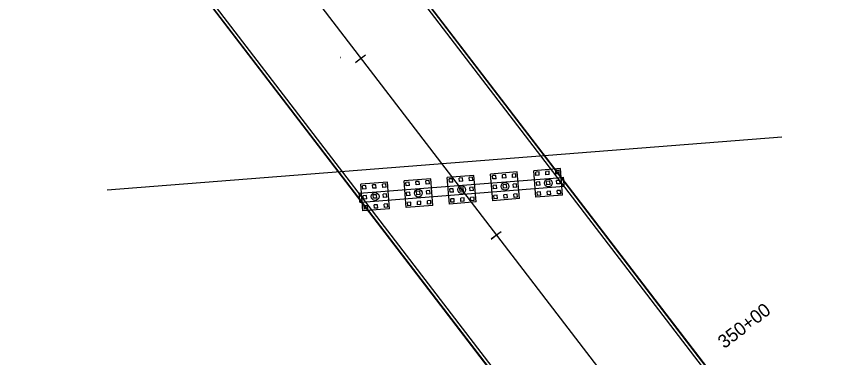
# Model space of a CAD drawing. Extents: x 881426 to 887360, y 1564404 to 1567430.
# Drawn here: x 884000 to 884363.6, y 1565295.5 to 1565449 of the extents above; entities that cross this region are included whole.
import ezdxf

# ---------------------------------------------------------------- set-up
doc = ezdxf.new("R2010")
doc.units = 0
for name, color, linetype in [('B_Concrete', 7, 'Continuous'), ('B_Concrete hidden', 7, 'Continuous'), ('R_Horz Alg', 7, 'Continuous'), ('R_Horz Alg Annot', 7, 'Continuous'), ('S_EXIST_ROW', 7, 'Continuous'), ('S_MSC_PT_SYM', 7, 'Continuous')]:
    doc.layers.add(name, color=color, linetype=linetype)

msp = doc.modelspace()

# ---------------------------------------------------------------- linework, layer by layer
at = {"layer": 'B_Concrete'}
for p, q in [((884362.37, 1565220.93), (884071.12, 1565600.88)), ((884363.42, 1565221.74), (884072.18, 1565601.69)), ((884363.42, 1565221.74), (884072.18, 1565601.69)), ((884363.56, 1565221.85), (884072.31, 1565601.79)), ((884302.84, 1565175.31), (884011.59, 1565555.25)), ((884301.65, 1565174.39), (884010.4, 1565554.34)), ((884301.78, 1565174.49), (884010.54, 1565554.44)), ((884301.78, 1565174.49), (884010.54, 1565554.44)), ((884244.95, 1565376.57), (884245.75, 1565376.63)), ((884245.84, 1565375.41), (884245.75, 1565376.63)), ((884154.34, 1565365.47), (884154.24, 1565366.69)), ((884154.34, 1565365.47), (884155.13, 1565365.53))]:
    msp.add_line(p, q, dxfattribs=at)
at = {"layer": 'B_Concrete hidden'}
for p, q in [((884244.44, 1565380.54), (884232.47, 1565379.61)), ((884245.37, 1565368.58), (884244.44, 1565380.54)), ((884154.03, 1565369.46), (884244.95, 1565376.57)), ((884205.55, 1565377.5), (884193.59, 1565376.57)), ((884194.53, 1565364.6), (884193.59, 1565376.57)), ((884204.87, 1565376.7), (884203.37, 1565376.58)), ((884203.49, 1565375.08), (884203.37, 1565376.58)), ((884204.98, 1565375.2), (884204.87, 1565376.7)), ((884206.49, 1565365.54), (884205.55, 1565377.5)), ((884225, 1565379.02), (884213.03, 1565378.09)), ((884213.97, 1565366.12), (884213.03, 1565378.09)), ((884215.33, 1565377.51), (884213.84, 1565377.4)), ((884213.96, 1565375.9), (884213.84, 1565377.4)), ((884215.45, 1565376.02), (884215.33, 1565377.51)), ((884219.82, 1565377.87), (884218.32, 1565377.75)), ((884218.44, 1565376.25), (884218.32, 1565377.75)), ((884219.94, 1565376.37), (884219.82, 1565377.87)), ((884224.31, 1565378.22), (884222.81, 1565378.1)), ((884222.93, 1565376.6), (884222.81, 1565378.1)), ((884224.42, 1565376.72), (884222.93, 1565376.6)), ((884224.42, 1565376.72), (884224.31, 1565378.22)), ((884225.93, 1565367.06), (884225, 1565379.02)), ((884233.41, 1565367.64), (884232.47, 1565379.61)), ((884234.77, 1565379.03), (884233.28, 1565378.92)), ((884233.4, 1565377.42), (884233.28, 1565378.92)), ((884234.89, 1565377.54), (884233.4, 1565377.42)), ((884234.89, 1565377.54), (884234.77, 1565379.03)), ((884239.26, 1565379.39), (884237.77, 1565379.27)), ((884237.88, 1565377.77), (884237.77, 1565379.27)), ((884239.38, 1565377.89), (884237.88, 1565377.77)), ((884239.38, 1565377.89), (884239.26, 1565379.39)), ((884243.75, 1565379.74), (884242.25, 1565379.62)), ((884242.37, 1565378.12), (884242.25, 1565379.62)), ((884243.86, 1565378.24), (884242.37, 1565378.12)), ((884243.86, 1565378.24), (884243.75, 1565379.74)), ((884166.67, 1565374.46), (884154.71, 1565373.53)), ((884155.65, 1565361.56), (884154.71, 1565373.53)), ((884157.01, 1565372.95), (884155.52, 1565372.84)), ((884155.63, 1565371.34), (884155.52, 1565372.84)), ((884157.13, 1565371.46), (884157.01, 1565372.95)), ((884161.5, 1565373.3), (884160, 1565373.19)), ((884160.12, 1565371.69), (884160, 1565373.19)), ((884161.62, 1565371.81), (884161.5, 1565373.3)), ((884165.98, 1565373.65), (884164.49, 1565373.54)), ((884164.61, 1565372.04), (884164.49, 1565373.54)), ((884166.1, 1565372.16), (884165.98, 1565373.65)), ((884167.61, 1565362.5), (884166.67, 1565374.46)), ((884186.11, 1565375.98), (884174.15, 1565375.05)), ((884175.09, 1565363.08), (884174.15, 1565375.05)), ((884176.45, 1565374.47), (884174.96, 1565374.36)), ((884175.07, 1565372.86), (884174.96, 1565374.36)), ((884176.57, 1565372.98), (884175.07, 1565372.86)), ((884176.57, 1565372.98), (884176.45, 1565374.47)), ((884180.94, 1565374.82), (884179.44, 1565374.71)), ((884179.56, 1565373.21), (884179.44, 1565374.71)), ((884181.06, 1565373.33), (884179.56, 1565373.21)), ((884181.06, 1565373.33), (884180.94, 1565374.82)), ((884185.43, 1565375.18), (884183.93, 1565375.06)), ((884184.05, 1565373.56), (884183.93, 1565375.06)), ((884185.54, 1565373.68), (884184.05, 1565373.56)), ((884185.54, 1565373.68), (884185.43, 1565375.18)), ((884187.05, 1565364.02), (884186.11, 1565375.98)), ((884195.89, 1565375.99), (884194.4, 1565375.88)), ((884194.51, 1565374.38), (884194.4, 1565375.88)), ((884196.01, 1565374.5), (884194.51, 1565374.38)), ((884196.01, 1565374.5), (884195.89, 1565375.99)), ((884200.38, 1565376.34), (884198.88, 1565376.23)), ((884199, 1565374.73), (884198.88, 1565376.23)), ((884200.5, 1565374.85), (884199, 1565374.73)), ((884200.5, 1565374.85), (884200.38, 1565376.34)), ((884204.98, 1565375.2), (884203.49, 1565375.08)), ((884215.45, 1565376.02), (884213.96, 1565375.9)), ((884215.68, 1565373.03), (884214.19, 1565372.91)), ((884214.31, 1565371.42), (884214.19, 1565372.91)), ((884215.8, 1565371.53), (884215.68, 1565373.03)), ((884219.94, 1565376.37), (884218.44, 1565376.25)), ((884220.17, 1565373.38), (884218.68, 1565373.26)), ((884218.79, 1565371.77), (884218.68, 1565373.26)), ((884220.29, 1565371.88), (884220.17, 1565373.38)), ((884224.66, 1565373.73), (884223.16, 1565373.61)), ((884223.28, 1565372.12), (884223.16, 1565373.61)), ((884224.77, 1565372.23), (884224.66, 1565373.73)), ((884235.13, 1565374.55), (884233.63, 1565374.43)), ((884233.75, 1565372.94), (884233.63, 1565374.43)), ((884235.24, 1565373.05), (884233.75, 1565372.94)), ((884235.24, 1565373.05), (884235.13, 1565374.55)), ((884239.61, 1565374.9), (884238.12, 1565374.78)), ((884238.23, 1565373.29), (884238.12, 1565374.78)), ((884239.73, 1565373.4), (884238.23, 1565373.29)), ((884239.73, 1565373.4), (884239.61, 1565374.9)), ((884244.1, 1565375.25), (884242.6, 1565375.13)), ((884242.72, 1565373.64), (884242.6, 1565375.13)), ((884244.21, 1565373.75), (884242.72, 1565373.64)), ((884244.21, 1565373.75), (884244.1, 1565375.25)), ((884246.06, 1565372.65), (884245.84, 1565375.41)), ((884154.24, 1565366.69), (884154.03, 1565369.46)), ((884155.13, 1565365.53), (884246.06, 1565372.65)), ((884157.13, 1565371.46), (884155.63, 1565371.34)), ((884161.62, 1565371.81), (884160.12, 1565371.69)), ((884166.1, 1565372.16), (884164.61, 1565372.04)), ((884176.8, 1565369.99), (884175.31, 1565369.87)), ((884175.42, 1565368.37), (884175.31, 1565369.87)), ((884176.92, 1565368.49), (884176.8, 1565369.99)), ((884181.29, 1565370.34), (884179.79, 1565370.22)), ((884179.91, 1565368.73), (884179.79, 1565370.22)), ((884181.41, 1565368.84), (884181.29, 1565370.34)), ((884185.78, 1565370.69), (884184.28, 1565370.57)), ((884184.4, 1565369.08), (884184.28, 1565370.57)), ((884185.89, 1565369.19), (884184.4, 1565369.08)), ((884185.89, 1565369.19), (884185.78, 1565370.69)), ((884196.24, 1565371.51), (884194.75, 1565371.39)), ((884194.87, 1565369.9), (884194.75, 1565371.39)), ((884196.36, 1565370.01), (884194.87, 1565369.9)), ((884196.36, 1565370.01), (884196.24, 1565371.51)), ((884200.73, 1565371.86), (884199.23, 1565371.74)), ((884199.35, 1565370.25), (884199.23, 1565371.74)), ((884200.85, 1565370.36), (884199.35, 1565370.25)), ((884200.85, 1565370.36), (884200.73, 1565371.86)), ((884205.22, 1565372.21), (884203.72, 1565372.09)), ((884203.84, 1565370.6), (884203.72, 1565372.09)), ((884205.33, 1565370.71), (884203.84, 1565370.6)), ((884205.33, 1565370.71), (884205.22, 1565372.21)), ((884215.8, 1565371.53), (884214.31, 1565371.42)), ((884220.29, 1565371.88), (884218.79, 1565371.77)), ((884224.77, 1565372.23), (884223.28, 1565372.12)), ((884225.01, 1565369.24), (884223.51, 1565369.13)), ((884225.13, 1565367.75), (884225.01, 1565369.24)), ((884235.48, 1565370.06), (884233.98, 1565369.95)), ((884234.1, 1565368.45), (884233.98, 1565369.95)), ((884235.59, 1565368.57), (884235.48, 1565370.06)), ((884239.96, 1565370.41), (884238.47, 1565370.3)), ((884238.58, 1565368.8), (884238.47, 1565370.3)), ((884240.08, 1565368.92), (884239.96, 1565370.41)), ((884244.45, 1565370.76), (884242.95, 1565370.65)), ((884243.07, 1565369.15), (884242.95, 1565370.65)), ((884244.57, 1565369.27), (884243.07, 1565369.15)), ((884244.57, 1565369.27), (884244.45, 1565370.76)), ((884157.36, 1565368.47), (884155.87, 1565368.35)), ((884155.98, 1565366.85), (884155.87, 1565368.35)), ((884157.48, 1565366.97), (884155.98, 1565366.85)), ((884157.48, 1565366.97), (884157.36, 1565368.47)), ((884161.85, 1565368.82), (884160.35, 1565368.7)), ((884160.47, 1565367.2), (884160.35, 1565368.7)), ((884161.97, 1565367.32), (884160.47, 1565367.2)), ((884161.97, 1565367.32), (884161.85, 1565368.82)), ((884166.34, 1565369.17), (884164.84, 1565369.05)), ((884164.96, 1565367.56), (884164.84, 1565369.05)), ((884166.45, 1565367.67), (884164.96, 1565367.56)), ((884166.45, 1565367.67), (884166.34, 1565369.17)), ((884176.92, 1565368.49), (884175.42, 1565368.37)), ((884181.41, 1565368.84), (884179.91, 1565368.73)), ((884181.64, 1565365.85), (884180.15, 1565365.73)), ((884180.26, 1565364.24), (884180.15, 1565365.73)), ((884181.76, 1565364.36), (884181.64, 1565365.85)), ((884186.13, 1565366.2), (884184.63, 1565366.09)), ((884184.75, 1565364.59), (884184.63, 1565366.09)), ((884186.24, 1565364.71), (884186.13, 1565366.2)), ((884196.59, 1565367.02), (884195.1, 1565366.9)), ((884195.22, 1565365.41), (884195.1, 1565366.9)), ((884196.71, 1565365.53), (884196.59, 1565367.02)), ((884201.08, 1565367.37), (884199.59, 1565367.26)), ((884199.7, 1565365.76), (884199.59, 1565367.26)), ((884201.2, 1565365.88), (884199.7, 1565365.76)), ((884201.2, 1565365.88), (884201.08, 1565367.37)), ((884205.57, 1565367.72), (884204.07, 1565367.61)), ((884204.19, 1565366.11), (884204.07, 1565367.61)), ((884205.68, 1565366.23), (884204.19, 1565366.11)), ((884205.68, 1565366.23), (884205.57, 1565367.72)), ((884225.93, 1565367.06), (884213.97, 1565366.12)), ((884216.04, 1565368.54), (884214.54, 1565368.42)), ((884214.66, 1565366.93), (884214.54, 1565368.42)), ((884216.15, 1565367.05), (884214.66, 1565366.93)), ((884216.15, 1565367.05), (884216.04, 1565368.54)), ((884220.52, 1565368.89), (884219.03, 1565368.78)), ((884219.14, 1565367.28), (884219.03, 1565368.78)), ((884220.64, 1565367.4), (884219.14, 1565367.28)), ((884220.64, 1565367.4), (884220.52, 1565368.89)), ((884223.63, 1565367.63), (884223.51, 1565369.13)), ((884225.13, 1565367.75), (884223.63, 1565367.63)), ((884245.37, 1565368.58), (884233.41, 1565367.64)), ((884235.59, 1565368.57), (884234.1, 1565368.45)), ((884240.08, 1565368.92), (884238.58, 1565368.8)), ((884167.61, 1565362.5), (884155.65, 1565361.56)), ((884157.71, 1565363.98), (884156.22, 1565363.86)), ((884156.34, 1565362.37), (884156.22, 1565363.86)), ((884157.83, 1565362.48), (884156.34, 1565362.37)), ((884157.83, 1565362.48), (884157.71, 1565363.98)), ((884162.2, 1565364.33), (884160.7, 1565364.21)), ((884160.82, 1565362.72), (884160.7, 1565364.21)), ((884162.32, 1565362.84), (884160.82, 1565362.72)), ((884162.32, 1565362.84), (884162.2, 1565364.33)), ((884166.69, 1565364.68), (884165.19, 1565364.56)), ((884165.31, 1565363.07), (884165.19, 1565364.56)), ((884166.8, 1565363.19), (884165.31, 1565363.07)), ((884166.8, 1565363.19), (884166.69, 1565364.68)), ((884187.05, 1565364.02), (884175.09, 1565363.08)), ((884177.15, 1565365.5), (884175.66, 1565365.38)), ((884175.78, 1565363.89), (884175.66, 1565365.38)), ((884177.27, 1565364.01), (884175.78, 1565363.89)), ((884177.27, 1565364.01), (884177.15, 1565365.5)), ((884181.76, 1565364.36), (884180.26, 1565364.24)), ((884186.24, 1565364.71), (884184.75, 1565364.59)), ((884206.49, 1565365.54), (884194.53, 1565364.6)), ((884196.71, 1565365.53), (884195.22, 1565365.41))]:
    msp.add_line(p, q, dxfattribs=at)
for centre in [(884219.48, 1565372.57), (884238.92, 1565374.09), (884161.16, 1565368.01), (884180.6, 1565369.53), (884200.04, 1565371.05)]:
    msp.add_circle(centre, 1.75, dxfattribs=at)
at = {"layer": 'R_Horz Alg'}
msp.add_line((883399.11, 1566415.89), (884332.67, 1565198.04), dxfattribs=at)
at = {"layer": 'R_Horz Alg Annot'}
for p, q in [((884152.66, 1565428.47), (884156.9, 1565431.72)), ((884213.5, 1565349.11), (884217.73, 1565352.35))]:
    msp.add_line(p, q, dxfattribs=at)
for points in [[(884152.4, 1565428.27), (884154.78, 1565430.1)], [(884213.24, 1565348.91), (884215.62, 1565350.73)]]:
    msp.add_lwpolyline(points, dxfattribs=at)
at = {"layer": 'S_EXIST_ROW'}
msp.add_line((884343.82, 1565394.64), (884040.84, 1565370.89), dxfattribs=at)
at = {"layer": 'S_MSC_PT_SYM'}
msp.add_lwpolyline([(884145.58, 1565430.48), (884145.58, 1565430.53), (884145.58, 1565430.48), (884145.53, 1565430.48), (884145.58, 1565430.48), (884145.58, 1565430.43), (884145.58, 1565430.48), (884145.63, 1565430.48)], dxfattribs=at)
msp.add_lwpolyline([(884145.58, 1565430.48), (884145.58, 1565430.53), (884145.58, 1565430.48), (884145.53, 1565430.48), (884145.58, 1565430.48), (884145.58, 1565430.43), (884145.58, 1565430.48), (884145.63, 1565430.48)], dxfattribs=at)

# ---------------------------------------------------------------- texts
at = {"layer": 'R_Horz Alg Annot'}
msp.add_text('350+00', height=6, rotation=37.4722, dxfattribs=at).set_placement((884317.96, 1565299.41))

doc.saveas('drawing.dxf')
